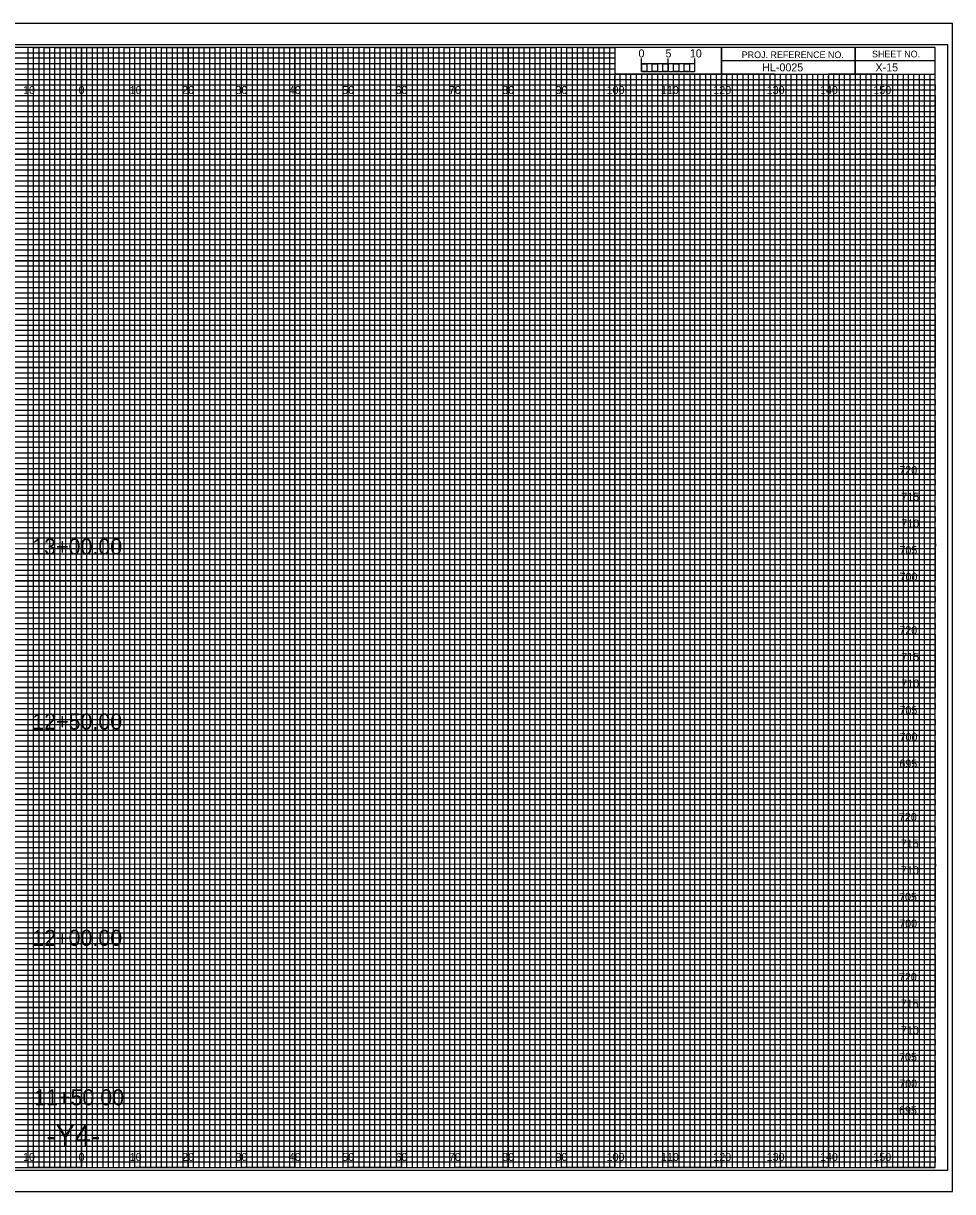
# Model space of a CAD drawing. Extents: x -13 to 323, y -5 to 434.
# Drawn here: x 149.1 to 323.3, y 215.5 to 434.5 of the extents above; entities that cross this region are included whole.
import ezdxf

# ---------------------------------------------------------------- set-up
doc = ezdxf.new("R2010")
doc.units = 0
for name, color, linetype in [('Exist CMT Pavement', 7, 'Continuous'), ('Exist Cross Section Cell', 7, 'Continuous'), ('Exist XS Center Line Elevation Label', 7, 'Continuous'), ('Exist XS Ground Line', 7, 'Continuous'), ('Prop CMT Pvmt Course 1 Wedge', 7, 'Continuous'), ('Prop CMT Pvmt Course 2', 7, 'Continuous'), ('Prop CMT Pvmt Course 3', 7, 'Continuous'), ('Prop CMT Pvmt Surface', 7, 'Continuous'), ('Prop CMT Pvmt Surface Shoulder', 7, 'Continuous'), ('Prop CMT Pvmt Wedge Surface 1', 7, 'Continuous'), ('Prop CMT Pvmt Wedge Surface 2', 7, 'Continuous'), ('Prop CMT Pvmt Wedge Surface 3', 7, 'Continuous'), ('Prop CMT Shld Paved Course 1', 7, 'Continuous'), ('Prop CMT Shld Paved Course 2', 7, 'Continuous'), ('Prop CMT Shld Paved Course 3', 7, 'Continuous'), ('Prop CMT Subgrade Earthwork', 7, 'Continuous'), ('Scratch_Level_1', 7, 'Continuous')]:
    doc.layers.add(name, color=color, linetype=linetype)

msp = doc.modelspace()

# ---------------------------------------------------------------- linework, layer by layer
at = {"layer": 'Exist XS Center Line Elevation Label'}
for points in [[(145, 220), (155, 220), (155, 430), (165, 430), (165, 220), (175, 220), (175, 430), (185, 430), (185, 220), (195, 220), (195, 430), (205, 430), (205, 220), (215, 220), (215, 430), (225, 430), (225, 220), (235, 220), (235, 430), (245, 430), (245, 220), (255, 220), (255, 430), (259.93, 430), (260, 430), (260, 425), (264.99, 425), (264.99, 220), (275, 220), (275, 425), (285, 425), (285, 220), (295, 220), (295, 425), (305, 425), (305, 220), (315, 220), (315, 425)], [(0, 425), (275, 425)], [(0, 405), (320, 405), (320, 415), (0, 415)], [(0, 385), (320, 385), (320, 395), (0, 395)], [(0, 365), (320, 365), (320, 375), (0, 375)], [(0, 345), (320, 345), (320, 355), (0, 355)], [(0, 325), (320, 325), (320, 335), (0, 335)], [(0, 305), (320, 305), (320, 315), (0, 315)], [(0, 285), (320, 285), (320, 295), (0, 295)], [(0, 265), (320, 265), (320, 275), (0, 275)], [(0, 245), (320, 245), (320, 255), (0, 255)], [(0, 225), (320, 225), (320, 235), (0, 235)]]:
    msp.add_lwpolyline(points, dxfattribs=at)
at = {"layer": 'Exist XS Ground Line'}
for p, q in [((150, 430), (140, 430)), ((150, 220), (150, 430)), ((170, 430), (160, 430)), ((160, 430), (160, 220)), ((170, 220), (170, 430)), ((190, 430), (180, 430)), ((180, 430), (180, 220)), ((190, 220), (190, 430)), ((210, 430), (200, 430)), ((200, 430), (200, 220)), ((210, 220), (210, 430)), ((230, 430), (220, 430)), ((220, 430), (220, 220)), ((230, 220), (230, 430)), ((250, 430), (240, 430)), ((240, 430), (240, 220)), ((250, 220), (250, 430)), ((260, 430), (260, 220)), ((270, 220), (270, 425)), ((290, 425), (280, 425)), ((280, 425), (280, 220)), ((290, 220), (290, 425)), ((310, 425), (300, 425)), ((300, 425), (300, 220)), ((310, 220), (310, 425)), ((160, 220), (150, 220)), ((180, 220), (170, 220)), ((200, 220), (190, 220)), ((220, 220), (210, 220)), ((240, 220), (230, 220)), ((260, 220), (250, 220)), ((280, 220), (270, 220)), ((300, 220), (290, 220)), ((320, 220), (310, 220)), ((320, 220), (320, 220))]:
    msp.add_line(p, q, dxfattribs=at)
for points in [[(0, 420), (320, 420), (320, 410), (0, 410)], [(0, 400), (320, 400), (320, 390), (0, 390)], [(0, 380), (320, 380), (320, 370), (0, 370)], [(0, 360), (320, 360), (320, 350), (0, 350)], [(0, 340), (320, 340), (320, 330), (0, 330)], [(0, 320), (320, 320), (320, 310), (0, 310)], [(0, 300), (320, 300), (320, 290), (0, 290)], [(0, 280), (320, 280), (320, 270), (0, 270)], [(0, 260), (320, 260), (320, 250), (0, 250)], [(0, 240), (320, 240), (320, 230), (0, 230)]]:
    msp.add_lwpolyline(points, dxfattribs=at)
at = {"layer": 'Prop CMT Pvmt Course 1 Wedge'}
for p, q in [((323.3, 434.5), (-13.4, 434.5)), ((-13.4, 215.5), (323.3, 215.5))]:
    msp.add_line(p, q, dxfattribs=at)
at = {"layer": 'Prop CMT Pvmt Course 2'}
msp.add_lwpolyline([(-13.4, 215.5), (323.3, 215.5), (323.3, 434.5), (-13.4, 434.5)], close=True, dxfattribs=at)
at = {"layer": 'Prop CMT Pvmt Course 3'}
msp.add_lwpolyline([(-10.8, 219.5), (322.4, 219.5), (322.4, 430.5), (-10.8, 430.5)], close=True, dxfattribs=at)
at = {"layer": 'Prop CMT Shld Paved Course 1'}
for p, q in [((305, 430), (305, 425)), ((305, 425), (305, 430)), ((280, 427.5), (280, 425)), ((320, 427.49), (280, 427.49)), ((280, 425), (320, 425))]:
    msp.add_line(p, q, dxfattribs=at)
for points in [[(320, 430), (0, 430), (0, 220), (320, 220)], [(280, 430), (260, 430), (260, 425.03), (280, 425.03)], [(320, 430), (280, 430), (280, 425), (320, 425)]]:
    msp.add_lwpolyline(points, close=True, dxfattribs=at)
at = {"layer": 'Prop CMT Shld Paved Course 2'}
for p, q in [((267, 425), (266.01, 425)), ((266.01, 425), (266.01, 220)), ((267, 220), (267, 425)), ((269, 425), (268, 425)), ((268, 425), (268, 220)), ((269, 220), (269, 425)), ((266.01, 220), (265, 220)), ((268, 220), (267, 220))]:
    msp.add_line(p, q, dxfattribs=at)
for points in [[(150, 220), (151, 220), (151, 430), (152, 430), (152, 220)], [(152, 220), (153, 220), (153, 430), (154, 430), (154, 220)], [(155, 220), (156, 220), (156, 430), (157, 430), (157, 220)], [(157, 220), (158, 220), (158, 430), (159, 430), (159, 220)], [(160, 220), (161, 220), (161, 430), (162, 430), (162, 220)], [(162, 220), (163, 220), (163, 430), (164, 430), (164, 220)], [(165, 220), (166, 220), (166, 430), (167, 430), (167, 220)], [(167, 220), (168, 220), (168, 430), (169, 430), (169, 220)], [(170, 220), (171, 220), (171, 430), (172, 430), (172, 220)], [(172, 220), (173, 220), (173, 430), (174, 430), (174, 220)], [(175, 220), (176, 220), (176, 430), (177, 430), (177, 220)], [(177, 220), (178, 220), (178, 430), (179, 430), (179, 220)], [(180, 220), (181, 220), (181, 430), (182, 430), (182, 220)], [(182, 220), (183, 220), (183, 430), (184, 430), (184, 220)], [(185, 220), (186, 220), (186, 430), (187, 430), (187, 220)], [(187, 220), (188, 220), (188, 430), (189, 430), (189, 220)], [(190, 220), (191, 220), (191, 430), (192, 430), (192, 220)], [(192, 220), (193, 220), (193, 430), (194, 430), (194, 220)], [(195, 220), (196, 220), (196, 430), (197, 430), (197, 220)], [(197, 220), (198, 220), (198, 430), (199, 430), (199, 220)], [(200, 220), (201, 220), (201, 430), (202, 430), (202, 220)], [(202, 220), (203, 220), (203, 430), (204, 430), (204, 220)], [(205, 220), (206, 220), (206, 430), (207, 430), (207, 220)], [(207, 220), (208, 220), (208, 430), (209, 430), (209, 220)], [(210, 220), (211, 220), (211, 430), (212, 430), (212, 220)], [(212, 220), (213, 220), (213, 430), (214, 430), (214, 220)], [(215, 220), (216, 220), (216, 430), (217, 430), (217, 220)], [(217, 220), (218, 220), (218, 430), (219, 430), (219, 220)], [(220, 220), (221, 220), (221, 430), (222, 430), (222, 220)], [(222, 220), (223, 220), (223, 430), (224, 430), (224, 220)], [(225, 220), (226, 220), (226, 430), (227, 430), (227, 220)], [(227, 220), (228, 220), (228, 430), (229, 430), (229, 220)], [(230, 220), (231, 220), (231, 430), (232, 430), (232, 220)], [(232, 220), (233, 220), (233, 430), (234, 430), (234, 220)], [(235, 220), (236, 220), (236, 430), (237, 430), (237, 220)], [(237, 220), (238, 220), (238, 430), (239, 430), (239, 220)], [(240, 220), (241, 220), (241, 430), (242, 430), (242, 220)], [(242, 220), (243, 220), (243, 430), (244, 430), (244, 220)], [(245, 220), (246, 220), (246, 430), (247, 430), (247, 220)], [(247, 220), (248, 220), (248, 430), (249, 430), (249, 220)], [(250, 220), (251, 220), (251, 430), (252, 430), (252, 220)], [(252, 220), (253, 220), (253, 430), (254, 430), (254, 220)], [(255, 220), (256, 220), (256, 430), (257, 430), (257, 220)], [(257, 220), (258, 220), (258, 430), (259, 430), (259, 220)], [(260, 220), (261, 220), (261, 425), (262.02, 425), (262.02, 220)], [(262, 220), (263, 220), (263, 425), (263.99, 425), (263.99, 220)], [(270, 220), (270.98, 220), (270.98, 425), (272, 425), (272, 220)], [(272, 220), (273, 220), (273, 425), (274.05, 425), (274.05, 220)], [(275, 220), (276, 220), (276, 425), (277, 425), (277, 220)], [(277, 220), (278, 220), (278, 425), (279, 425), (279, 220)], [(280, 220), (281, 220), (281, 425), (282, 425), (282, 220)], [(282, 220), (283, 220), (283, 425), (284, 425), (284, 220)], [(285, 220), (286, 220), (286, 425), (287, 425), (287, 220)], [(287, 220), (288, 220), (288, 425), (289, 425), (289, 220)], [(290, 220), (291, 220), (291, 425), (292, 425), (292, 220)], [(292, 220), (293, 220), (293, 425), (294, 425), (294, 220)], [(295, 220), (296, 220), (296, 425), (297, 425), (297, 220)], [(297, 220), (298, 220), (298, 425), (299, 425), (299, 220)], [(300, 220), (301, 220), (301, 425), (302, 425), (302, 220)], [(302, 220), (303, 220), (303, 425), (304, 425), (304, 220)], [(305, 220), (306, 220), (306, 425), (307, 425), (307, 220)], [(307, 220), (308, 220), (308, 425), (309, 425), (309, 220)], [(310, 220), (311, 220), (311, 425), (312, 425), (312, 220)], [(312, 220), (313, 220), (313, 425), (314, 425), (314, 220)], [(315, 220), (316, 220), (316, 425), (317, 425), (317, 220)], [(317, 220), (318, 220), (318, 425), (319, 425), (319, 220)]]:
    msp.add_lwpolyline(points, dxfattribs=at)
at = {"layer": 'Prop CMT Shld Paved Course 3'}
for p, q in [((265, 425.49), (265, 427.9)), ((265, 426.9), (265, 427.9)), ((270, 425.49), (270, 427.9)), ((275, 425.49), (275, 427.9)), ((275, 426.9), (275, 427.9))]:
    msp.add_line(p, q, dxfattribs=at)
for points in [[(275, 426.9), (265, 426.9), (265, 425.49), (275, 425.49)], [(265, 426.9), (266, 426.9), (266, 425.49), (265, 425.49)], [(267, 426.9), (268, 426.9), (268, 425.49), (267, 425.49)], [(269, 426.9), (270, 426.9), (270, 425.49), (269, 425.49)], [(271, 426.9), (272, 426.9), (272, 425.49), (271, 425.49)], [(273, 426.9), (274, 426.9), (274, 425.49), (273, 425.49)]]:
    msp.add_lwpolyline(points, close=True, dxfattribs=at)
at = {"layer": 'Prop CMT Subgrade Earthwork'}
for p, q in [((150, 220), (150, 430)), ((160, 220), (160, 430)), ((170, 220), (170, 430)), ((180, 220), (180, 430)), ((190, 220), (190, 430)), ((200, 220), (200, 430)), ((210, 220), (210, 430)), ((220, 220), (220, 430)), ((230, 220), (230, 430)), ((240, 220), (240, 430)), ((250, 220), (250, 430)), ((260, 220), (260, 424.69)), ((270, 220), (270, 424.69)), ((280, 220), (280, 424.69)), ((290, 220), (290, 424.69)), ((300, 220), (300, 424.69)), ((310, 220), (310, 424.69)), ((0, 420), (320, 420)), ((0, 410), (320, 410)), ((0, 400), (320, 400)), ((0, 390), (320, 390)), ((0, 380), (320, 380)), ((0, 370), (320, 370)), ((0, 360), (320, 360)), ((0, 350), (320, 350)), ((0, 340), (320, 340)), ((0, 330), (320, 330)), ((0, 320), (320, 320)), ((0, 310), (320, 310)), ((0, 300), (320, 300)), ((0, 290), (320, 290)), ((0, 280), (320, 280)), ((0, 270), (320, 270)), ((0, 260), (320, 260)), ((0, 250), (320, 250)), ((0, 240), (320, 240)), ((0, 230), (320, 230))]:
    msp.add_line(p, q, dxfattribs=at)
at = {"layer": 'Scratch_Level_1'}
for p, q in [((0, 429), (260, 429)), ((260, 427.98), (0, 427.98)), ((260, 429), (260, 427.98)), ((0, 427), (260, 427)), ((260, 425.89), (0, 425.89)), ((260, 427), (260, 425.89)), ((0, 424), (320, 424))]:
    msp.add_line(p, q, dxfattribs=at)
for points in [[(0, 423), (270, 423), (320, 423), (320, 422), (0, 422)], [(0, 421), (320, 421), (320, 419), (0, 419)], [(0, 418), (320, 418), (320, 417), (0, 416.98)], [(0, 416), (320, 416), (320, 414), (0, 414)], [(0, 413), (320, 413), (320, 412), (0, 412)], [(0, 411), (320, 411), (320, 409), (0, 409)], [(0, 408), (320, 408), (320, 407), (0, 407)], [(0, 406), (320, 406), (320, 404), (0, 404)], [(0, 403), (320, 403), (320, 402), (0, 402)], [(0, 401), (320, 401), (320, 399), (0, 399)], [(0, 398), (320, 398), (320, 397), (0, 397)], [(0, 396), (320, 396), (320, 393.95), (320, 393), (320, 392), (0, 392)], [(0, 394), (320, 394), (320, 393), (0, 393)], [(0, 391), (320, 391), (320, 389), (0, 389.03)], [(0, 389.03), (320, 389), (320, 388), (0, 388)], [(0, 387), (320, 387), (320, 386), (0, 386)], [(0, 384), (320, 384), (320, 383), (0, 383)], [(0, 382), (320, 382), (320, 381), (0, 381)], [(-0.07, 378.89), (320, 378.89), (320, 377.88), (-0.07, 377.88)], [(0, 377), (320, 377), (320, 376), (0, 376)], [(0, 374), (320, 374), (320, 373), (0, 373)], [(0, 372), (320, 372), (320, 371), (0, 371)], [(0, 369), (320, 369), (320, 368), (0, 368)], [(0, 367), (320, 367), (320, 366), (0, 366)], [(0, 364), (320, 364), (320, 363), (0, 363)], [(0, 362), (320, 362), (320, 361), (0, 361)], [(0, 359), (320, 359), (319.99, 357.98), (0, 358)], [(0, 357), (320, 357), (320, 356), (0, 356)], [(0, 354), (320, 354), (320, 353), (0, 353)], [(0, 352), (320, 352), (320, 351), (0, 351)], [(0, 349), (320, 349), (320, 348), (0, 348)], [(0, 347), (320, 347), (320, 346), (0, 346)], [(0, 344), (320, 344), (320, 343), (0, 343)], [(0, 342), (320, 342), (320, 341), (0, 341)], [(0, 339), (320, 339), (320, 338), (0, 338)], [(0, 336.99), (320.07, 336.91), (320, 336), (0, 336)], [(0, 334), (320, 334), (320, 333), (0, 333)], [(0, 332), (320, 332), (320, 331), (0, 331)], [(0, 329), (320, 329), (320, 328), (0, 328)], [(0, 327), (320, 327), (320, 326), (0, 326)], [(0, 324), (320, 324), (320, 323), (0, 323)], [(0, 322), (320, 322), (320, 321), (0, 321)], [(0, 319), (320, 319), (320, 318), (0, 318)], [(0, 317), (320, 317), (320, 316), (0, 316)], [(0, 314), (320, 314), (320, 313), (0, 313)], [(0, 312), (320, 312), (320, 311), (0, 311)], [(0, 309), (320, 309), (320, 308), (0, 308)], [(0, 307), (320, 307), (320, 306), (0, 306)], [(0, 304), (320, 304), (320, 303), (0, 303)], [(0, 302), (320, 302), (320, 301), (0, 301)], [(0, 299), (320, 299), (319.99, 297.98), (0, 298)], [(0, 297), (320, 297), (320, 296), (0, 296)], [(0, 294), (320, 294), (320, 293), (0, 293)], [(0, 292), (320, 292), (320, 291), (0, 291)], [(0, 289), (320, 289), (320, 288), (0, 288)], [(0, 287), (320, 287), (320, 286), (0, 286)], [(0, 284), (320, 284), (320, 283), (0, 283)], [(0, 282), (320, 282), (320, 281), (0, 281)], [(0, 279), (320, 279), (320, 278), (0, 278)], [(0, 276.99), (320.07, 276.91), (320, 276), (0, 276)], [(0, 274), (320, 274), (320, 273), (0, 273)], [(0, 272), (320, 272), (320, 271), (0, 271)], [(0, 269), (320, 269), (320, 268), (0, 268)], [(0, 267), (320, 267), (320, 266), (0, 266)], [(0, 264), (320, 264), (320, 263), (0, 263)], [(0, 262), (320, 262), (320, 261), (0, 261)], [(0, 259), (320, 259), (320, 258), (0, 258)], [(0, 257), (320, 257), (320, 256), (0, 256)], [(0, 254), (320, 254), (320, 253), (0, 253)], [(0, 252), (320, 252), (320, 251), (0, 251)], [(0, 249), (320, 249), (320, 248), (0, 248)], [(0, 247), (320, 247), (320, 246), (0, 246)], [(0, 244), (320, 244), (320, 243), (0, 243)], [(0, 242), (320, 242), (320, 241), (0, 241)], [(0, 239), (320, 239), (320, 238), (0, 238)], [(0, 237), (320, 237), (320, 236), (0, 236)], [(0, 234), (320, 234), (320, 233), (0, 233)], [(0, 232), (320, 232), (320, 231), (0, 231)], [(0, 229), (320, 229), (320, 228), (0, 228)], [(0, 227), (320, 227), (320, 226), (0, 226)], [(0, 224), (320, 224), (320, 223), (0, 223)], [(0, 222), (320, 222), (320, 221), (0, 221)]]:
    msp.add_lwpolyline(points, dxfattribs=at)

# ---------------------------------------------------------------- texts
at = {"layer": 'Exist CMT Pavement'}
for s, p in [('720', (313.31, 350)), ('715', (313.67, 345)), ('710', (313.68, 340)), ('705', (313.33, 335)), ('700', (313.35, 330)), ('720', (313.31, 320)), ('715', (313.67, 315)), ('710', (313.68, 310)), ('705', (313.33, 305)), ('700', (313.35, 300)), ('695', (313.32, 295)), ('720', (313.23, 285)), ('715', (313.59, 280)), ('710', (313.61, 275)), ('705', (313.26, 270)), ('700', (313.28, 265)), ('720', (313.23, 255)), ('715', (313.59, 250)), ('710', (313.61, 245)), ('705', (313.26, 240)), ('700', (313.28, 235)), ('695', (313.25, 230))]:
    msp.add_text(s, height=1.5, dxfattribs=at).set_placement(p)
at = {"layer": 'Exist Cross Section Cell'}
for s, p in [('10', (149.04, 421.25)), ('0', (159.45, 421.25)), ('0', (159.45, 421.25)), ('10', (169.04, 421.25)), ('20', (178.86, 421.25)), ('30', (188.86, 421.25)), ('40', (198.86, 421.25)), ('50', (208.86, 421.25)), ('60', (218.86, 421.25)), ('70', (228.86, 421.25)), ('80', (238.86, 421.25)), ('90', (248.86, 421.25)), ('100', (258.44, 421.25)), ('110', (268.62, 421.25)), ('120', (278.44, 421.25)), ('130', (288.44, 421.25)), ('140', (298.44, 421.25)), ('150', (308.44, 421.25)), ('10', (149.04, 221.25)), ('0', (159.45, 221.25)), ('0', (159.45, 221.25)), ('10', (169.04, 221.25)), ('20', (178.86, 221.25)), ('30', (188.86, 221.25)), ('40', (198.86, 221.25)), ('50', (208.86, 221.25)), ('60', (218.86, 221.25)), ('70', (228.86, 221.25)), ('80', (238.86, 221.25)), ('90', (248.86, 221.25)), ('100', (258.44, 221.25)), ('110', (268.62, 221.25)), ('120', (278.44, 221.25)), ('130', (288.44, 221.25)), ('140', (298.44, 221.25)), ('150', (308.44, 221.25))]:
    msp.add_text(s, height=1.5, dxfattribs=at).set_placement(p)
at = {"layer": 'Prop CMT Pvmt Surface'}
for s, p in [('13+00.00', (150.77, 334.92)), ('12+50.00', (150.77, 302.13)), ('12+00.00', (150.77, 261.57)), ('11+50.00', (151.13, 231.68))]:
    msp.add_text(s, height=3, dxfattribs=at).set_placement(p)
at = {"layer": 'Prop CMT Pvmt Surface Shoulder'}
for s, p in [('5', (269.47, 428.12)), ('10', (274.04, 428.12))]:
    msp.add_text(s, height=1.5, dxfattribs=at).set_placement(p)
at = {"layer": 'Prop CMT Pvmt Wedge Surface 1'}
msp.add_text('X-15', height=1.5, dxfattribs=at).set_placement((308.83, 425.5))
at = {"layer": 'Prop CMT Pvmt Wedge Surface 2'}
msp.add_text('HL-0025', height=1.5, dxfattribs=at).set_placement((287.6, 425.5))
at = {"layer": 'Prop CMT Pvmt Wedge Surface 3'}
msp.add_text('-Y4-', height=4, dxfattribs=at).set_placement((153.39, 224))
at = {"layer": 'Prop CMT Shld Paved Course 1'}
for s, p in [('PROJ. REFERENCE NO.', (283.77, 427.99)), ('SHEET NO.', (308.19, 428.12))]:
    msp.add_text(s, height=1.25, dxfattribs=at).set_placement(p)
at = {"layer": 'Prop CMT Shld Paved Course 3'}
msp.add_text('0', height=1.5, dxfattribs=at).set_placement((264.41, 428.12))

doc.saveas('drawing.dxf')
